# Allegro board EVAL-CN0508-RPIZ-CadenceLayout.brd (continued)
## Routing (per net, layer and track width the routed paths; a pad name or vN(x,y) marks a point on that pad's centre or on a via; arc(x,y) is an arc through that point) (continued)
INTVCC: length 67.2
  TOP w0.305: U1.21 22.49,37.71 v1(22.48,37.72) 22.48,38.24 C5.1 ; v1(59.82,37.21) 59.82,37.47 59.69,37.59 59.69,43.25 59.99,43.56 R28.1 ; DS1.A 6.26,33.99 v1(20.24,33.99) U1.1
  L3_VCC w0.305: v1(20.24,33.99) 20.24,35.86 22.1,37.72 v1(22.48,37.72)
  BOTTOM w0.305: v1(22.48,37.72) 22.99,37.21 v1(59.82,37.21)
LDOIN: length 80.3
  TOP w0.203: R4.2 20.53,40.26 21.28,39.52 21.28,38.05 21.99,37.33 U1.22
  TOP w0.305: R42.1 77.38,34.08 v1(77.34,34.04) ; v1(18.78,41.27) C6.2 18.43,39.89 R8.1 v1(12.54,39.89) ; C8.1 32.58,34.82 33.02,35.26 v1(33.02,35.31) ; R4.2 v1(20.43,41.3) ; R7.1 v1(9.27,34.94)
  TOP w0.508: R57.1 v1(60.58,52.2)
  L3_VCC w0.305: v1(9.27,34.94) 12.54,38.21 v1(12.54,39.89) ; v1(33.02,34.29) 26.01,41.3 v1(20.43,41.3) ; v1(18.78,41.27) 19.67,42.16 26.16,42.16 v1(33.02,35.31)
  L3_VCC w0.508: v1(39.5,52.58) 41.13,50.95 56.71,50.95 58.72,52.96 59.82,52.96 v1(60.58,52.2)
M5V0: length 38.1
  TOP w0.508: U6.2 68.37,42.68 C41.1 ; v1(68.9,37.34) R44.1 68.9,42.82 C41.1 ; D4.1 70.26,43.01 C41.1 ; JP1.1 v1(86.18,47.78)
  BOTTOM w0.508: v1(68.9,37.34) 85.67,37.34 86.18,37.85 v1(86.18,47.78)
MISO: length 26.7
  TOP w0.203: U9.28 50.93,50.84 50.93,51.72 51.02,51.82 51.02,53.63 50.82,53.83 50.82,56.62 45.85,61.59 43.56,61.59 40.64,64.52 JP4.2 40.64,69.09 41.15,69.6 P3.21
MOSI: length 47.8
  TOP w0.203: P3.19 38.61,65.53 43.18,60.96 45.85,60.96 50.41,56.4 v1(50.41,52.07) 50.41,51.84 50.43,51.82 50.43,50.84 U9.29 ; U10.8 v1(68.39,54.68)
  BOTTOM w0.203: v1(68.39,54.68) 68.34,54.74 58.36,54.74 56.81,53.19 53.44,53.19 52.32,52.07 v1(50.41,52.07)
Net_3:
  vias: v1(60.71,44.7)
R_ILIM: length 64.9
  TOP w0.305: R61.1 v1(57.92,45.72)
  TOP w0.889: TP3.1 103.49,47.81 R14.3
  BOTTOM w0.635: R14.3 103.49,52.34 96.14,59.69 81.66,59.69 78.61,56.64 78.61,52.96 76.2,50.55 60.1,50.55 56.91,47.36 56.91,46.46 57.66,45.72 v1(57.92,45.72)
R_VLIM: length 83.9
  TOP w0.305: R63.1 57.57,47.24 v1(57.81,47.01)
  TOP w0.508: v1(57.81,47.01) 57.9,47.01
  TOP w0.635: R43.3 103.17,25.21 TP5.1 v1(95.38,44.32)
  BOTTOM w0.635: v1(57.81,47.01) 60.33,49.53 76.75,49.53 79.5,52.28 79.5,56.26 82.04,58.8 88.65,58.8 90.68,56.77 90.68,49.02 v1(95.38,44.32)
SCL_RPI: length 51.9
  TOP w0.305: v1(63.02,65.69) R40.1 63.18,66.82 U7.6
  BOTTOM w0.305: 20.83,71.63 22.63,69.82 63.74,69.82 64.58,68.98 64.58,67.25 v1(63.02,65.69)
SCLK: length 43
  TOP w0.203: U10.6 66.11,55.68 62.36,59.44 v1(48.89,59.44) 43.69,64.64 43.69,71.63 ; U9.30 49.93,50.84 49.93,51.69 49.8,51.82 49.8,54.85 v1(48.89,55.75)
  BOTTOM w0.203: v1(48.89,59.44) v1(48.89,55.75)
SDA_RPI: length 50.3
  TOP w0.305: U7.5 63.86,67.47 R39.1 63.41,68.71 v1(63.92,68.71)
  BOTTOM w0.305: P3.3 20.63,69.29 63.18,69.29 63.75,68.71 v1(63.92,68.71)
TEMP_1: length 102.7
  TOP w0.305: U11.2 v1(84.84,69.6) ; U2.11 48.6,20.06 R51.1 49.32,20.49 50.04,21.21 v1(50.04,21.34) ; R59.1 42.29,48.64 41.78,48.13 v1(41.78,44.07)
  L3_VCC w0.305: v1(41.78,44.07) 41.78,41.27 50.04,33.02 v1(50.04,21.34)
  BOTTOM w0.305: 41.91,44.07 v1(41.78,44.07) 41.78,59.18 44.2,61.59 63.75,61.59 73.69,71.53 82.91,71.53 v1(84.84,69.6)
TEMP_2: length 129.3
  TOP w0.305: R56.1 43.32,47.13 42.6,46.41 v1(42.6,44.07) ; U11.6 v1(79.76,70.87) ; R10.1 v1(89.51,20.72) 89.51,20.06 89.24,19.78 U3.11
  L3_VCC w0.305: v1(89.51,20.72) 89.51,26.95 85.47,30.99 53.59,30.99 44.15,40.43 44.15,42.69 44.12,42.72 44.12,44.22 43.73,44.6 43.19,44.6 42.65,44.07 v1(42.6,44.07)
  BOTTOM w0.305: v1(42.6,44.07) 42.6,58.85 44.7,60.96 63.84,60.96 72.22,69.34 72.26,69.34 73.79,70.87 v1(79.76,70.87)
UART0_RX: length 32.5
  TOP w0.203: P10.1 6.35,58.04 7.62,59.31 7.62,62.99 12.45,67.82 21.84,67.82 24.64,70.61 24.64,72.9 P3.10
UART0_TX: length 28.8
  TOP w0.203: P3.8 22.1,72.9 22.1,70.61 19.81,68.33 12.06,68.33 6.73,62.99 6.73,60.45 5.59,59.31 3.56,59.31
UNNAMED_2_ADLT3081V2_I39_ILIM: length 83.4
  TOP w0.356: v1(89.37,10.54) 89.24,10.67 U3.6 ; U2.6 v1(48.6,11.56) 48.6,10.67 R13.1
  L3_VCC w0.305: v1(89.37,10.54) 91.11,12.28 91.11,17.42 90.75,17.78 88.27,17.78 87,19.05 87,26.29 84.07,29.21 57.4,29.21 56.36,28.17 56.36,21.49 58.25,19.6 58.25,18.26 55.75,15.76 55.75,11.68 53.85,9.78 50.38,9.78 v1(48.6,11.56)
UNNAMED_2_ADLT3081V2_I63_OUT1: length 4.2
  TOP w0.356: 85.98,16.51 85.99,16.52 U3.16
  BOTTOM w0.635: R17.1 67.93,17.5 ; R17.1 67.93,16.03 ; R17.1 68.71,16.76
  vias: v1(68.2,14.86) v1(68.2,13.59) v1(68.2,12.32) v1(68.2,11.05) v1(69.47,14.86) v1(69.47,13.59) v1(69.47,12.32) v1(69.47,11.05) v1(69.47,9.78) v1(70.74,14.86) v1(70.74,13.59) v1(70.74,12.32) v1(70.74,11.05) v1(70.74,9.78) v1(70.74,8.51) v1(70.74,7.24) v1(72.01,14.86) v1(72.01,13.59) v1(72.01,12.32) v1(72.01,11.05) v1(72.01,9.78) v1(72.01,8.51) v1(72.01,7.24) v1(73.28,13.59) v1(73.28,12.32) v1(73.28,11.05) v1(73.28,9.78) v1(73.28,8.51) v1(73.28,7.24) v1(74.55,13.59) v1(74.55,12.32) v1(74.55,11.05) v1(74.55,9.78) v1(74.55,8.51) v1(74.55,7.24) v1(74.55,5.97) v1(74.55,4.7) v1(74.55,3.43) v1(75.82,13.59) v1(75.82,12.32) v1(75.82,11.05) v1(75.82,9.78) v1(75.82,8.51) v1(75.82,7.24) v1(75.82,5.97) v1(75.82,4.7) v1(75.82,3.43) v1(77.09,13.59) v1(77.09,12.32) v1(77.09,11.05) v1(77.09,9.78) v1(77.09,8.51) v1(77.09,7.24) v1(77.09,5.97) v1(77.09,4.7) v1(77.09,3.43) v1(78.36,13.59) v1(78.36,12.32) v1(78.36,11.05) v1(78.36,9.78) v1(78.36,8.51) v1(78.36,7.24) v1(78.36,5.97) v1(78.36,4.7) v1(78.36,3.43) v1(79.63,13.59) v1(79.63,12.32) v1(79.63,11.05) v1(79.63,9.78) v1(79.63,8.51) v1(79.63,7.24) v1(79.63,5.97) v1(79.63,4.7) v1(79.63,3.43) v1(80.9,13.59) v1(80.9,12.32) v1(80.9,11.05) v1(80.9,9.78) v1(80.9,8.51) v1(80.9,7.24) v1(80.9,5.97) v1(80.9,4.7) v1(80.9,3.43) v1(82.17,13.59) v1(82.17,12.32) v1(82.17,11.05) v1(82.17,9.78) v1(82.17,8.51) v1(82.17,7.24) v1(82.17,5.97) v1(82.17,4.7) v1(82.17,3.43) v1(83.44,13.59) v1(83.44,12.32) v1(83.44,11.05) v1(83.44,9.78) v1(83.44,8.51) v1(83.44,7.24) v1(83.44,5.97) v1(83.44,4.7) v1(83.44,3.43) v1(84.71,13.59) v1(84.71,12.32) v1(84.71,11.05) v1(84.71,9.78) v1(84.71,8.51) v1(84.71,7.24) v1(84.71,5.97) v1(84.71,4.7) v1(84.71,3.43) v1(85.98,16.26) v1(85.98,14.99) v1(85.98,11.05) v1(85.98,9.78) v1(85.98,8.51) v1(85.98,7.24) v1(85.98,5.97) v1(85.98,4.7) v1(85.98,3.43) v1(86.79,16.76) v1(86.79,15.62) v1(86.79,14.48) v1(87.25,11.05) v1(87.25,9.78) v1(87.25,8.51) v1(87.25,7.24) v1(87.25,5.97) v1(87.25,4.7) v1(87.25,3.43) v1(87.53,16.76) v1(87.53,15.62) v1(87.53,14.48) v1(88.27,16.76) v1(88.27,15.62) v1(88.27,14.48) v1(88.52,11.05) v1(88.52,9.78) v1(88.52,8.51) v1(88.52,7.24) v1(88.52,5.97) v1(88.52,4.7) v1(88.52,3.43) v1(89,16.76) v1(89,15.62) v1(89,14.48) v1(89.74,16.76) v1(89.74,15.62) v1(89.74,14.48) v1(89.79,9.78) v1(89.79,8.64) v1(89.79,8.51) v1(89.79,7.24) v1(89.79,5.97) v1(89.79,4.7) v1(89.79,3.43) v1(90.42,16.76) v1(90.42,15.62) v1(90.42,14.48) v1(91.06,7.24) v1(91.06,5.97) v1(91.06,4.7) v1(91.06,3.43) v1(92.33,18.67) v1(92.33,17.4) v1(92.33,16.13) v1(92.33,14.86) v1(92.33,13.59) v1(92.33,12.32) v1(92.33,7.24) v1(92.33,5.97) v1(92.33,4.7) v1(92.33,3.43) v1(93.6,19.94) v1(93.6,18.67) v1(93.6,17.4) v1(93.6,16.13) v1(93.6,14.86) v1(93.6,13.59) v1(93.6,12.32) v1(93.6,11.05) v1(93.6,9.78) v1(93.6,8.51) v1(93.6,7.24) v1(93.6,5.97) v1(93.6,4.7) v1(93.6,3.43) v1(94.87,21.21) v1(94.87,19.94) v1(94.87,18.67) v1(94.87,17.4) v1(94.87,16.13) v1(94.87,14.86) v1(94.87,13.59) v1(94.87,12.32) v1(94.87,11.05) v1(94.87,9.78) v1(94.87,8.51) v1(94.87,7.24) v1(94.87,5.97) v1(94.87,4.7) v1(94.87,3.43) v1(96.14,21.21) v1(96.14,19.94) v1(96.14,18.67) v1(96.14,17.4) v1(96.14,16.13) v1(96.14,14.86) v1(96.14,13.59) v1(96.14,12.32) v1(96.14,11.05) v1(96.14,9.78) v1(96.14,8.51) v1(96.14,7.24) v1(96.14,5.97) v1(96.14,4.7) v1(96.14,3.43) v1(97.41,21.21) v1(97.41,19.94) v1(97.41,18.67) v1(97.41,17.4) v1(97.41,16.13) v1(97.41,14.86) v1(97.41,13.59) v1(97.41,12.32) v1(97.41,11.05) v1(97.41,9.78) v1(97.41,8.51) v1(97.41,7.24) v1(97.41,5.97) v1(97.41,4.7) v1(97.41,3.43) v1(101.22,21.21) v1(101.22,19.94) v1(101.22,18.67) v1(101.22,17.4) v1(101.22,16.13) v1(101.22,14.86) v1(101.22,13.59) v1(101.22,12.32) v1(101.22,11.05) v1(101.22,9.78) v1(101.22,8.51) v1(101.22,7.24) v1(101.22,5.97) v1(101.22,2.16) v1(102.49,21.21) v1(102.49,19.94) v1(102.49,18.67) v1(102.49,17.4) v1(102.49,16.13) v1(102.49,14.86) v1(102.49,13.59) v1(102.49,12.32) v1(102.49,11.05) v1(102.49,9.78) v1(102.49,8.51) v1(102.49,7.24) v1(102.49,5.97) v1(102.49,2.16) v1(102.74,4.83) v1(102.74,3.43)
UNNAMED_2_ADLT8612_I115_BST: length 2.1
  TOP w0.305: C4.1 23.14,38.35 23.14,37.45 22.99,37.3 U1.20
UNNAMED_2_ADLT8612_I115_FB: length 2.3
  TOP w0.203: R5.1 19.48,37.07 19.67,36.88 U1.24
UNNAMED_2_ADLT8612_I115_PG: length 2.3
  TOP w0.203: U1.23 21.49,37.21 20.98,37.72 20.65,37.72 20.43,37.94 R4.1
UNNAMED_2_ADLT8612_I115_RT: length 3.8
  TOP w0.203: U1.3 21.99,33.42 21.17,32.6 21.17,31.58 21,31.41 R1.2
UNNAMED_2_ADLT8612_I115_TR: length 1.8
  TOP w0.203: U1.2 21.49,33.66 21.11,33.27 20.92,33.27 C3.1
UNNAMED_2_CAP_I50_N1: length 6.1
  TOP w0.305: C6.1 17.8,38.64 17.08,37.92 R5.2 R6.1 16.75,35.87 Q1.3
UNNAMED_2_DIOLED_I132_N: length 1.4
  TOP w0.305: R46.2 DS1.C
UNNAMED_2_RES_I24_N1: length 6.6
  TOP w0.203: U1.4 22.49,33.29 21.58,32.37 21.58,31.04 20.84,30.31 R3.2 20.22,29.53 20.25,29.5 R2.1
UNNAMED_2_RES_I51_N2: length 1.5
  TOP w0.305: Q1.2 13.42,34.94 R7.2
UNNAMED_2_RES_I53_N1: length 2.9
  TOP w0.305: R8.2 13.48,36.86 Q1.1 13.43,36.81 R9.1
UNNAMED_3_741G04_I85_Y: length 2.2
  TOP w0.305: U12.4 80.72,65.8 R70.1
UNNAMED_3_ADCMP392_I76_IN: length 10.8
  TOP w0.508: U11.5 83.57,72.14 84.84,70.87 U11.3 88.61,70.87 R67.2 ; R67.2 R66.1 ; R67.2 R68.1
UNNAMED_3_ADCMP392_I76_OUT: length 14.2
  TOP w0.305: U12.2 84.59,65.14 86.22,65.14
  TOP w0.508: U11.7 83.31,69.6 84.58,68.33 U11.1 88.43,68.33 R68.2 R69.1 87.72,66.64 86.22,65.14
UNNAMED_3_CN2P_I67_N2: length 29
  TOP w0.508: v1(83.97,61.47) Q3.3 ; D5.A 100.83,69.85 99.44,69.85 98.81,70.48 R71.1 98.81,72.14 P12.2
  TOP w0.635: D5.A v1(101.08,68.34)
  BOTTOM w0.635: v1(101.08,68.34) 99.99,67.25 93.92,67.25 88.14,61.47 v1(83.97,61.47)
UNNAMED_3_CN40PV2_I40_N8: length 13.5
  TOP w0.203: JP4.1 39.8,72.34 39.37,72.77 34.92,72.77 P3.16
UNNAMED_3_CN40PV2_I40_N11: length 9.1
  TOP w0.203: JP4.3 41.48,68.66 42.28,69.46 42.28,73.04 P3.22
UNNAMED_3_CN40PV2_I41_N7: length 6
  TOP w0.203: JP2.1 30.4,69.9 30.99,70.49 P3.13
UNNAMED_3_CN40PV2_I41_N8: length 5.8
  TOP w0.203: P3.15 33.53,70.23 33.83,69.93 JP3.1
UNNAMED_3_CN40PV2_I41_N16: length 56.3
  TOP w0.305: v1(17.78,69.6) 17.75,69.62 9.8,69.62 7.87,67.69 3.02,67.69 2.94,67.77 2.7,67.77 2.59,67.87 DS2.A ; P3.31 v1(53.85,68.58)
  BOTTOM w0.305: v1(17.78,69.6) 18.8,68.58 v1(53.85,68.58)
UNNAMED_3_CN40PV2_I41_N17: length 59.1
  TOP w0.305: DS3.A 2.59,66.86 2.92,67.18 8.51,67.18 10.29,68.96 v1(17.27,68.96) ; P3.33 v1(56.39,68.58)
  BOTTOM w0.305: v1(56.39,68.58) 56.39,68.33 55.98,67.92 53.57,67.92 53.55,67.94 18.29,67.94 v1(17.27,68.96)
UNNAMED_3_DIOLED_I48_N: length 1.2
  TOP w0.305: R20.2 DS2.C
UNNAMED_3_DIOLED_I49_N: length 1.3
  TOP w0.305: R21.2 DS3.C
UNNAMED_3_DIOLED_I84_N: length 1.3
  TOP w0.508: DS4.C R71.2
UNNAMED_3_RES_I68_N2: length 1.8
  TOP w0.305: Q3.1 80.64,64.17 R70.2
UNNAMED_3_RES_I87_N2: length 45.3
  TOP w0.305: P3.11 27.3,70.49 26.92,70.49 23.11,66.67 23.11,50.29 22.31,49.49 6.78,49.49 R19.2 4.95,49.44 S1.2
UNNAMED_4_ADLT6015_I86_: length 6.8
  TOP w0.305: A2.4 87.96,43.7 R26.1 R29.1 R75.1
UNNAMED_4_ADLT6015_I86__1: length 2.2
  TOP w0.508: JP5.2 90.14,37.75 A2.3
UNNAMED_4_ADLT6015_I86_OUT: length 6.2
  TOP w0.508: A2.1 83.4,37.75 ; 83.4,37.75 D2.C ; 83.4,37.75 83.61,37.54 R33.2 R41.1
UNNAMED_4_ADLT6015_I87_V: length 16.4
  TOP w0.305: A2.2 87.03,37.77 C30.2 87.03,48.02 JP1.2
  TOP w0.406: C34.2 87.01,49.93 ; 87.01,49.93 JP1.2 ; 87.01,49.93 A1.2
UNNAMED_4_ADLT6015_I97_: length 5.5
  TOP w0.305: A1.4 87.96,57.74 R27.1 R30.1 87.97,59.44 R74.1
UNNAMED_4_ADLT6015_I97_OUT: length 5.5
  TOP w0.508: A1.1 86.03,53.09 D3.C 84.19,51.08 R35.1 R34.2
UNNAMED_4_ADLT8609_I129_INTVCC: length 2.1
  TOP w0.203: C27.1 13.33,62.06 U5.3
UNNAMED_4_ADLT8609_I129_PG: length 2
  TOP w0.203: U5.8 13.33,54.82 R24.1
UNNAMED_4_ADLT8609_I129_RT: length 2.8
  TOP w0.203: U5.4 12.83,61.66 12.57,61.93 11.9,61.93 R22.1
UNNAMED_4_ADLT8609_I129_TR: length 2.5
  TOP w0.203: U5.7 12.83,55.67 C28.1
UNNAMED_4_ADLTC1983X_I10_C: length 2.3
  TOP w0.305: C40.2 64.3,45.28 U6.4
UNNAMED_4_ADLTC1983X_I10_C_1: length 2.2
  TOP w0.305: U6.3 66.92,45.42 C40.1
UNNAMED_4_ADLTC1983X_I10_SHDNN: length 5.2
  TOP w0.508: U6.6 62.5,41.73 R32.1 R28.2 60.62,41.78 R31.2
UNNAMED_4_CAP_I64_N1: length 5.6
  TOP w0.203: C32.1 9.55,54.7 R25.1 R23.1 10.53,56.69 U5.6
UNNAMED_4_CAP_I177_N2: length 1.4
  TOP w0.508: R33.1 C38.2
UNNAMED_4_CAP_I182_N2: length 1.4
  TOP w0.508: R34.1 C39.2
UNNAMED_4_LINLT3092_I168_SET: length 2.1
  TOP w0.305: U8.5 33.87,50.97 34.29,50.55 34.29,49.41 R45.2
UNNAMED_4_RES_I70_N2: length 6.9
  TOP w0.508: R44.2 72.64,41.15 73.28,41.78 73.28,44.83 73.66,45.21 74.23,45.21 Q2.2
UNNAMED_6_AD568XRV2_I36_VREF: length 5.3
  TOP w0.305: U10.9 64.94,54.18 C56.1
  TOP w0.508: C56.1 C57.1 64.85,50.99 R65.2
UNNAMED_6_AD71244_I19_AIN0: length 2.1
  TOP w0.305: U9.4 48.2,48.62 46.21,48.62 R59.2
UNNAMED_6_AD71244_I19_AIN1: length 2.5
  TOP w0.305: U9.5 48.19,48.11 47.23,48.11 47.15,48.03 47.03,48.03 46.25,47.26 R56.2
UNNAMED_6_AD71244_I19_AIN2: length 2.4
  TOP w0.305: U9.8 48.16,46.64 47.13,45.61 R60.2
UNNAMED_6_AD71244_I19_AIN3: length 2.4
  TOP w0.305: R50.2 48.92,45.41 U9.9
UNNAMED_6_AD71244_I19_AIN4: length 1.7
  TOP w0.305: U9.16 52.42,44.26 R55.2
UNNAMED_6_AD71244_I19_AIN5: length 2.3
  TOP w0.305: U9.17 53.44,46.64 54.36,45.72 R61.2
UNNAMED_6_AD71244_I19_AIN6: length 2.4
  TOP w0.305: R63.2 55.03,47.33 54.36,48.01 54.11,48.01 53.98,48.14 U9.20 53.17,48.09 53.18,48.09
UNNAMED_6_AD71244_I19_AIN7: length 5.9
  TOP w0.203: R62.2 58.46,48.26 55.24,48.26 54.91,48.59 53.91,48.59 53.87,48.64 U9.21
UNNAMED_6_AD71244_I19_CLK: length 9.3
  TOP w0.203: U9.31 49.43,50.84 49.43,51.62 49.4,51.65 49.4,53.47 v1(48.89,53.98)
  TOP w0.254: v1(48.89,53.98) 47.62,55.24 R64.1 46.19,57.82 TP7.1
UNNAMED_6_AD71244_I19_REFOUT: length 2.2
  TOP w0.305: C50.2 54.76,49.05 53.85,49.05 53.76,49.14 U9.22
UNNAMED_6_AD71244_I19_REGCAPA: length 2.3
  TOP w0.305: U9.24 53.57,50.14 54.38,50.95 C52.1
UNNAMED_6_AD71244_I19_REGCAPD: length 4.8
  TOP w0.305: U9.1 48.23,50.14 48.23,52.61 47.52,53.32 C51.1
UNNAMED_6_CNTP1P_I52_N1: length 7.2
  TOP w0.305: U9.27 51.42,51.57 51.48,51.63 51.48,55.63 R54.2 51.6,57.7 TP6.1
UNNAMED_6_RES_I2_N1: length 3.1
  TOP w0.305: R52.2 R55.1 54.22,44.26 R53.1
UNNAMED_6_RES_I4_N1: length 3
  TOP w0.508: R48.2 45.89,42.54 R50.1 45.86,44.12 R49.1
UNNAMED_6_RES_I53_N2: length 3
  TOP w0.203: R58.1 R57.2 60.58,48.17 R62.1
VDAC: length 44.8
  TOP w0.305: U10.10 67.48,53.68 67.69,53.47 67.69,53.09
  TOP w0.635: v1(75.44,34.92) 75.44,36.83 77.22,38.61 77.22,47.24 74.8,49.66 67.95,49.66 67.31,50.29 TP8.1 67.69,51.69 67.69,53.09 ; JP5.1 v1(90.17,35.43)
  BOTTOM w0.635: v1(75.44,34.92) 89.66,34.92 v1(90.17,35.43)
VOUT: length 181.3
  TOP w0.508: v1(58.23,11.05) 58.1,10.92 57.47,10.92 57.02,11.37 57.02,15.77 56.66,16.13 56.01,16.13 55.56,15.68 55.56,7.43 54.99,6.86 P8.2 ; C21.2 68.81,4.69 P7.2 66.8,6.6 66.23,7.17 66.23,15.43 65.79,15.88 65.07,15.88 64.71,15.52 64.71,11.3 64.33,10.92 63.5,10.92 v1(63.37,11.05)
  TOP w0.635: D1.3 60.91,16.82 ; D1.3 59.79,16.82 ; D1.3 60.35,16.05
  TOP w0.762: 52.47,40.26 52.47,36.94 v1(54.23,35.18) 54.42,34.99 71.69,34.99 75.18,38.48 Q2.3 ; 52.47,40.26 R52.1 ; 52.47,40.26 41.66,40.26 40.77,41.15 40.77,52.96 37.85,55.88 27.3,55.88 24,52.58 24,43.05 23.24,42.29 11.05,42.29 10.23,41.48 R9.2
  L3_VCC w0.635: 57.78,5.21 VOUT.1 ; VOUT.1 60.83,8.26 ; VOUT.1 63.88,5.21
  BOTTOM w0.508: 57.65,17.5 57.65,17.79 56.64,18.8 56.64,32.77 v1(54.23,35.18)
  BOTTOM w0.635: 57.65,16.03 R18.2 ; R18.2 58.42,16.76 ; R18.2 57.65,17.5 ; 65.92,16.03 R17.2 ; R17.2 65.92,17.5 ; R17.2 65.15,16.76
  vias: v1(54.29,9.02) v1(54.29,7.75) v1(56.32,4.57) v1(56.32,3.3) v1(57.34,4.57) v1(57.34,3.3) v1(58.23,13.59) v1(58.23,12.32) v1(58.23,9.78) v1(58.36,8.51) v1(58.36,7.24) v1(58.42,2.92) v1(59.5,12.32) v1(59.5,11.05) v1(59.5,9.78) v1(59.5,8.51) v1(60.77,14.86) v1(60.77,13.59) v1(60.77,12.32) v1(60.77,11.05) v1(60.77,9.78) v1(60.77,8.51) v1(62.04,12.32) v1(62.04,8.51) v1(62.1,11.05) v1(62.1,9.78) v1(63.31,12.32) v1(63.31,9.78) v1(63.31,8.51) v1(63.31,7.24) v1(63.37,2.92) v1(64.45,4.57) v1(64.45,3.3) v1(65.47,4.57) v1(65.47,3.3) v1(67.25,9.27) v1(67.25,8)
VPOT: length 58.2
  TOP w0.508: A1.3 v1(88.77,53.12)
  TOP w0.635: TP4.1 106.35,25.75 R43.4
  BOTTOM w0.762: R43.4 105.16,25.23 105.16,35.81 101.22,39.75 97.66,39.75 88.27,49.15 88.27,52.61 v1(88.77,53.12)
VREF: length 161.6
  TOP w0.305: U9.12 50.43,45.93 50.43,44.7 51.07,44.05 C43.1
  TOP w0.508: R65.1 63.2,48.85 TP9.1 v1(63.12,46.99) 60.96,46.99 57.21,43.24 v1(57.21,35.88)
  TOP w0.635: R66.2 90.84,72.73 92.33,71.25 92.33,69.09 94.87,66.55 100.97,66.55 107.49,60.02 R14.5 107.82,50.09 107.82,46.61 ; R43.5 R43.6 109.49,44.94 107.82,46.61 ; C43.1 C44.1 v1(48.55,43.88) ; 107.82,46.61 107.19,45.97 93.22,45.97 92.58,45.34 92.58,39.24 v1(91.9,38.56) JP5.3
  BOTTOM w0.508: v1(91.9,38.56) 90.75,38.56 88.07,35.88 v1(57.21,35.88)
  BOTTOM w0.635: v1(63.12,46.99) 61.82,46.99 58.71,43.88 v1(48.55,43.88)
VSET: length 207.4
  TOP w0.356: C11.2 50.25,10.5 49.51,11.23 v1(49.51,11.62) 49.25,11.88 U2.7 ; U3.7 89.89,11.5 90.89,10.5 C13.2 v1(92.03,10.5)
  TOP w0.508: v1(79.08,34.04) R42.2 R41.2 80.56,37.31 D2.A 78.87,37.85 78.13,38.59 78.13,44.96 ; R35.2 82.51,52.74 82.15,53.1 80.93,53.1 D3.A ; 78.13,44.96 78.25,45.09 R29.2 R75.2 ; 78.13,44.96 78.13,52.73 78.49,53.09 D3.A ; 86.28,59.44 81.91,59.44 80.9,58.42 v1(80.9,54.48) 80.91,54.47 D3.A ; 86.28,59.44 86.27,59.44 R74.2 ; 86.28,59.44 R30.2 ; v1(33.27,47.12) 33.28,47.12 R45.1 32.32,49.4 R47.2
  TOP w0.762: 59.25,19.12 v1(57.59,19.12) ; 59.25,19.12 59.26,19.12 61.3,19.12 D1.1 ; 59.25,19.12 59.38,19.12 D1.2
  L3_VCC w0.305: v1(92.03,10.5) 91.62,10.91 91.62,18.75 91.57,18.8
  L3_VCC w0.508: 55.63,21.08 v1(57.59,19.12) 55.12,16.64 55.12,12.32 53.34,10.54 50.59,10.54 v1(49.51,11.62) ; 55.63,21.08 52.58,21.08 52.07,20.57 49.72,20.57 49.15,21.15 49.15,31.24 v1(33.27,47.12) ; 55.63,21.08 55.63,28.32 57.15,29.84 84.45,29.84 87.76,26.54 87.76,19.3 88.27,18.8 91.57,18.8 91.57,23.31 91.29,23.59 91.29,28.75 91.29,29.11 87.88,32.51 81.33,32.51 79.8,34.04 v1(79.08,34.04)
WP: length 117.5
  TOP w0.305: U4.7 53.09,65.78 55.37,63.5 61.85,63.5 63.75,65.41 63.75,65.86 64.06,66.17 U7.7 66.55,66.17 67.06,66.67 v1(67.06,68.96)
  L3_VCC w0.305: v1(67.06,68.96) 69.85,68.96 72.52,71.63 100.61,71.63 105.02,67.22 105.02,63.13 113.66,54.48 113.66,43.43 110.36,40.13 110.36,34.16 113.57,30.95 113.57,21.75 P9.2

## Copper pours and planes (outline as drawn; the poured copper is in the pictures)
3V3A on L3_VCC: 0.89,75.31 38.29,75.31 38.29,70.35 39.87,68.77 78.99,68.77 79.57,68.19 79.57,55 75.94,51.37 41.65,51.37 40.32,52.59 40.32,58.17 39.12,59.37 15.21,59.37 14.29,58.14 14.29,52.71 13.84,52.26 0.89,52.26
3V3D on BOTTOM: 72.65,59.37 75.12,59.37 75.12,52.33 74.42,51.63 59.81,51.63 58.16,49.97 54.49,49.97 53.98,50.48 46.61,50.48 46.29,50.8 46.29,52.9 56.9,52.9 58.42,54.42 71,54.42 72.58,56 72.58,59.3
5V_RPI on TOP: 95.76,75.31 98.93,75.31 98.93,72.77 98.3,72.14 98.3,67.44 98.17,67.31 96.27,67.31 95.5,68.07 95.5,75.06
5V_RPI on TOP: 19.05,56.01 19.05,67.06 19.3,67.31 22.35,67.31 22.61,67.06 22.61,56.01 22.35,55.75 19.3,55.75
5V_RPI on BOTTOM: 4.45,75.31 12.83,75.31 24.19,75.25 24.19,55.18 1.08,55.18 1.08,70.74 3.81,70.74 4.45,71.37
5V_RPI on L3_VCC: 79.89,68.77 113.84,68.77 113.84,51.82 109.09,47.07 109.09,31.56 0.89,31.56 0.89,51.63 14.1,51.63 14.92,52.45 14.92,57.93 15.53,58.74 38.86,58.74 39.69,57.91 39.69,52.31 41.41,50.74 76.2,50.74 80.2,54.73 80.2,68.46
AGND on TOP (solid shape): 85.22,23.75 85.22,17.65 84.96,17.4 66.8,17.4 64.26,19.94 51.82,19.94 51.82,21.46 51.56,21.72 51.26,21.72 50.93,21.84 50.59,21.72 50.37,21.72 50.22,21.81 50.04,21.84 50.02,21.84 49.94,21.87 49.91,21.95 49.91,24.26 51.43,25.78 83.19,25.78
AGND on TOP: 19.18,33.27 19.18,32.13 19.43,31.88 19.43,28.07 19.05,27.69 7.62,27.69 6.73,26.8 6.73,13.72 6.48,13.46 1.4,13.46 1.02,13.84 1.02,33.27 1.52,33.78 12.45,33.78 12.57,33.66 12.57,31.88 12.7,31.75 16.76,31.75 17.14,32.13 17.14,33.15 17.27,33.27
AGND on TOP: 70.36,5.59 72.14,5.59 72.39,5.33 72.39,1.27 72.14,1.02 70.36,1.02 70.1,1.27 70.1,5.33
AGND on TOP: 37.59,8.13 37.59,1.65 38.23,1.02 46.61,1.02 46.99,1.4 46.99,5.71 44.32,8.38 37.85,8.38
AGND on TOP: 14.99,57.91 15.11,57.78 15.11,56.39 15.24,56.26 17.02,56.26 17.53,55.75 17.53,54.23 18.03,53.72 18.03,50.93 18.16,50.8 21.34,50.8 21.72,51.18 21.72,55.12 21.59,55.24 18.92,55.24 17.91,56.26 17.91,61.98 15.62,61.98 15.11,61.47 15.11,60.07 14.73,59.69 9.14,59.69 8.89,59.44 8.89,58.04 9.02,57.91
AGND on TOP: 25.78,36.32 26.8,36.32 27.05,36.07 29.84,36.07 29.84,25.65 30.23,25.27 43.81,25.27 44.58,24.51 44.58,17.53 44.45,17.4 25.53,17.4 25.4,17.53 25.4,32.13 24.38,33.15 24.38,34.42 24.26,34.54 18.29,34.54 18.16,34.67 18.16,35.94 18.29,36.07 19.56,36.07 19.81,36.32 20.7,36.32 20.83,36.2 25.65,36.2
AGND on BOTTOM: 24.83,75.31 112.78,75.31 113.79,74.29 113.79,27.05 112.97,26.23 66.61,26.23 66.61,18.99 56.96,18.99 56.96,25.97 25.08,25.97 25.08,33.59 20.51,33.59 20.51,36.89 85.73,36.89 86.55,37.71 86.55,55.5 85.48,56.58 81.78,56.58 80.96,55.76 80.96,48.26 79.5,46.8 41.85,46.8 41.85,53.34 40.01,55.18 24.83,55.18 ; 1 cut-out
AGND on BOTTOM: 37.98,8.32 44.32,8.32 46.93,5.71 46.93,0.89 37.66,0.89 37.66,8
AGND on L2_GND: 0.89,75.31 113.84,75.31 113.84,0.89 0.89,0.89
AGND on L3_VCC: 38.1,8.45 44.19,8.45 46.93,5.71 46.93,0.89 37.66,0.89 37.66,8
AGND on L3_VCC: 38.93,75.31 113.84,75.31 113.84,69.41 40.14,69.41 38.93,70.62
VIN on TOP: 22.86,34.29 22.86,33.15 21.84,32.13 21.84,29.84 21.34,29.34 21.34,27.69 20.83,27.18 8.13,27.18 7.37,26.42 7.37,12.95 6.86,12.45 1.27,12.45 1.02,12.19 1.02,7.75 1.27,7.49 16.13,7.49 16.64,8 16.64,16.76 17.14,17.27 24.26,17.27 24.64,17.65 24.64,32.51 24.13,33.02 24.13,34.29
VIN on TOP: 13.72,57.28 14.73,57.28 14.86,57.15 14.86,56.26 15.24,55.88 16.64,55.88 16.76,55.75 16.76,51.05 16.64,50.93 14.35,50.93 14.22,51.05 14.22,55.12 13.72,55.63
VIN on BOTTOM: 82.05,55.94 85.21,55.94 85.92,55.24 85.92,37.98 85.47,37.53 19.88,37.53 19.88,32.96 24.45,32.96 24.45,21.34 23.62,20.51 7.94,20.51 7.94,1.21 5.78,1.21 5.46,1.52 5.46,4.7 4.32,5.84 1.08,5.84 1.08,54.55 39.75,54.55 41.21,53.08 41.21,46.16 79.76,46.16 81.6,48 81.6,55.49 ; 1 cut-out
(no net) on TOP: 86.36,17.14 86.23,17.27 86.23,19.05 85.72,19.05 85.72,16.64 85.47,16.38 68.07,16.38 67.56,15.88 67.56,10.92 69.34,9.14 69.34,6.1 69.47,5.97 72.64,5.97 72.9,5.71 72.9,1.27 73.28,0.89 103.5,0.89 104.01,1.4 104.01,22.86 103.63,23.24 90.68,23.24 90.42,22.99 90.42,19.18 90.3,19.05 90.3,17.27 90.17,17.14 ; 2 cut-outs
(no net) on TOP: 85.22,23.75 85.22,17.65 84.96,17.4 66.8,17.4 64.26,19.94 51.82,19.94 51.82,21.46 51.56,21.72 50.04,21.72 49.91,21.84 49.91,24.26 51.43,25.78 83.19,25.78
(no net) on TOP: 49.66,19.05 49.66,17.27 49.53,17.14 45.72,17.14 45.59,17.27 45.59,19.05 45.09,19.05 45.09,16.64 44.83,16.38 18.16,16.38 17.65,15.88 17.65,1.27 18.03,0.89 36.2,0.89 36.96,1.65 36.96,8.64 37.34,9.02 44.58,9.02 47.62,5.97 47.62,1.14 47.88,0.89 52.07,0.89 52.32,1.14 52.32,9.65 54.48,11.81 54.48,18.54 53.98,19.05 ; 1 cut-out
ILIM+ on TOP (solid shape): outline of 249 points within 17.65,0.89 54.48,19.05
ILIM+ on BOTTOM: 25.08,25.34 56.32,25.34 56.32,13.47 52.51,9.66 52.51,0.89 47.56,0.89 47.56,5.97 44.58,8.95 37.71,8.95 37.02,8.26 37.02,0.89 8.57,0.89 8.57,19.88 23.88,19.88 25.08,21.08
ILIM+ on L3_VCC: 0.89,30.92 60.39,30.92 60.39,17.21 55.49,17.21 54.8,16.51 54.8,12.07 52.01,9.28 52.01,0.89 47.56,0.89 47.56,5.97 44.45,9.08 37.84,9.08 37.02,8.26 37.02,0.89 0.89,0.89
LDOIN on TOP: 32.13,45.47 32.35,46 32.89,46.23 34.29,46.23 36.58,48.51 36.58,51.82 36.32,52.07 33.02,52.07 32.89,52.2 32.89,54.48 33.15,54.74 37.85,54.74 39.88,52.7 39.88,35.05 40.64,34.29 89.28,34.29 89.66,33.91 89.66,17.91 89.53,17.78 86.61,17.78 86.61,19.69 86.36,19.94 86.36,24 83.69,26.67 51.18,26.67 48.26,23.75 48.26,20.19 48.13,20.07 48.13,17.78 45.85,17.78 45.85,19.81 45.59,20.07 45.59,25.91 44.83,26.67 30.73,26.67 30.73,36.58 32.13,37.97
UNNAMED_2_ADLT3081V2_I63_OUT1 on TOP (solid shape): outline of 394 points within 67.56,0.89 104.01,23.24
UNNAMED_2_ADLT3081V2_I63_OUT1 on BOTTOM: 67.25,25.59 113.22,25.59 113.79,25.02 113.79,1.91 112.78,0.89 69.02,0.89 69.02,9.66 67.25,11.43
UNNAMED_2_ADLT3081V2_I63_OUT1 on L3_VCC: 61.02,30.92 90.04,30.92 90.04,30.86 93.09,27.81 93.09,24.13 93.85,23.37 113.84,23.37 113.84,0.89 68.26,0.89 68.26,9.66 66.74,11.18 66.74,16.13 65.66,17.21 61.02,17.21
UNNAMED_2_ADLT8612_I115_SW1 on TOP: 23.37,36.58 29.84,36.58 31.37,38.1 31.37,45.85 31.12,46.1 25.15,46.1 24.64,45.59 24.64,38.1 24.51,37.97 23.49,37.97 23.37,37.85
UNNAMED_4_ADLT8609_I129_BST on TOP: 14.22,60.33 14.22,62.99 14.35,63.12 15.37,63.12 15.37,62.23 14.86,61.72 14.86,61.34 14.73,61.21 14.73,60.45 14.61,60.33
UNNAMED_4_IND_I45_N1 on TOP: 13.72,60.33 13.97,60.33 13.97,63.5 14.35,63.88 15.75,63.88 16,63.63 16,62.87 17.4,62.87 17.53,62.99 17.53,67.06 17.4,67.18 13.97,67.18 13.46,66.67 13.46,61.98 13.72,61.72
UNNAMED_4_LINLT3092_I168_OUT1 on TOP: 31.62,52.45 31.62,50.8 30.61,49.78 30.61,48.13 30.35,47.88 28.07,47.88 27.81,48.13 27.81,52.07 28.19,52.45
VOUT on TOP: 63.75,1.27 63.37,0.89 62.99,0.89 58.29,0.89 58.04,1.14 58.04,9.65 57.98,9.72 57.98,17.27 63.5,17.27 63.75,17.02
VOUT on BOTTOM: 56.96,18.35 66.61,18.35 66.61,11.17 68.39,9.39 68.39,0.89 53.15,0.89 53.15,9.39 56.96,13.2
VOUT on L3_VCC: 60.96,16.57 65.4,16.57 66.1,15.87 66.1,10.92 67.63,9.39 67.63,0.89 52.64,0.89 52.64,9.01 55.44,11.81 55.44,16.25 55.76,16.57 60.45,16.57 60.57,16.45 60.84,16.45

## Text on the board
User.Comments: CR_1_2 | HEX NUT 1 | HEX NUT 2 | DETAIL A | INSTALL SCREW (M035074) AT 4 LOCATION | PRIMARY SIDE | SECONDARY SIDE | INSTALL SAFTEY JACK CT2236 (MO35590) | SEE DETAIL A | PCB | SEE NOTE #6 | 5.    APPLY SOLDER LED AND SHORT THE 2 PINS OF THE FOLLOWING JUMPER | 4.    RoHS COMPLIANCE: ASSEMBLY VENDOR SHOULD ASSURE COMPLIANCE | 6.    INSTAL THE KNOB (M042481) TO THE POTENTIOMETER SHAFT | JP3: PIN 1 AND 2 | P7: PIN 1 AND 2 | P8: PIN 1 AND 2 | JP1: PIN 1 AND 2 | JP2: PIN 1 AND 2 | JP4: PIN 1 AND 2 | JP5: PIN 1 AND 2 | WITH LEAD-FREE AND RoHS PCB ASSEMBLY STANDARDS (EU RoHS | DIRECTIVE 2002/95/EC). | KNOB (M042481)
Ref Des/Silkscreen Top: A | C | EVAL-CN0508-RPIZ
PAGE_OUTLINE: A | B | C | D | INITIAL RELEASE | ECR-089087 | ECR-092924 | ECR-094242 | 14MAY19 | 07NOV19 | 29JAN20 | 31MAR20 | T. CABILDO | EVALUATION BOARD Z
DIMENSION: REF | " " | DIA MAX
User.11: A | C | 1 | 3
User.12: INSTALL STANDOFF (M032310 AT 4 LOCATION | 1. DO NOT TRIM DOWN P3 EXCESS PIN ON PRIMARY SIDE | ASSEMBLY NOTES 2:
User.15: L3_VCC  PLANE   (LAYER 2) | ROHS COMPLIANCE NOTE: HOMOGENOUS MATERIALS IN THIS BOARD SHALL BE COMPLIANT | THE EU RoHS DIRECTIVE 2002/95/EC | 3.5 MILS
User.17: L2 GND | 08-      -07
User.18: L3 VCC | 08-      -08
User.45: FIGURE | SIZE | 12.0 | 28.0 | 40.0 | 45.0 | 50.0 | 160.0 | 125.0 | 87.0x79.0 | 98.0x31.0 | 138.0x31.0 | PLATED | NON-PLATED | DRILL CHART: TOP to BOTTOM | ALL UNITS ARE IN MILS | QTY | 957 | 10 | 14 | 45 | 2 | 6 | 4 | 1 | TOLERANCE/NOTES
